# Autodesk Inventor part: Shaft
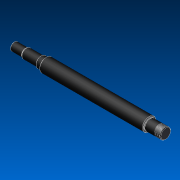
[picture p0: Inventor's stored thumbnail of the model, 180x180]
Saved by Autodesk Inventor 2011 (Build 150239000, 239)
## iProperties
Created: 2011-05
Part Number: Shaft
Material: Steel
Document SubType Name: Modeling
Designer: 904Chiaki
Density: 1 g/cm^3
Author: 904Chiaki
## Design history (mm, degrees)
sketch "Main Sketch"
  geometry: L1 (0, 0)-(545.5, 0) reference; L2 (0, 0)-(0, 15); L3 (0, 15)-(45, 15); L4 (45, 15)-(45, 17.5); L5 (45, 17.5)-(100, 17.5); L6 (100, 17.5)-(100, 20); L7 (100, 20)-(119, 20); L8 (119, 25)-(504.5, 25); L9 (545.5, 20)-(545.5, 0); L10 (504.5, 20)-(545.5, 20); L11 (119, 20)-(119, 25); L12 (504.5, 25)-(504.5, 20)
  constraints: 24 end point, 6 vertical, 2 horizontal
  dimensions: "d3" = 30 diameter of L3 L1 (derived); "d4" = 35 diameter of L5 L1 (derived); "d5" = 40 diameter of L7 L1 (derived); "d6" = 50 diameter of L8 L1 (derived); "d8" = 40 diameter of L10 L1 (derived)
revolve "Revolution1" sketch "Main Sketch" stored, may be unused: angle "d9" = 0 deg
chamfer "Chamfer15" distance "d52" = 1; stored, may be unused: second distance "d53" = 0.125, angle "d54" = 45 deg
chamfer "Chamfer16" distance "d55" = 1; stored, may be unused: second distance "d56" = 0.125, angle "d57" = 45 deg
node "Keyway1"
node "Relief2"
chamfer "Chamfer8" distance "d31" = 1; stored, may be unused: second distance "d32" = 0.125, angle "d33" = 45 deg
node "Relief3"
chamfer "Chamfer2" distance "d13" = 1; stored, may be unused: second distance "d14" = 0.125, angle "d15" = 45 deg
node "Relief1"
workpoint "Work Point1"
hole "Hole1" diameter "d60" = 8; stored, may be unused: countersink angle "d64" = 90 deg, drill point angle "d66" = 118 deg; dims "d58" = 10, "d59" = 10, "d61" = 6, "d62" = 4, "d63" = 2, "d65" = 30
chamfer "Chamfer17" distance "d67" = 1; stored, may be unused: second distance "d68" = 2, angle "d69" = 45 deg
thread "Thread1" dims "d70" = 10, "d71" = 0
sketch "Sketch5"
  geometry: C1 r 20 at (0, 0) reference
extrude "Extrusion1" join sketch "Sketch5" distance "d83" = 20; taper "d84" = 0 deg
chamfer "Chamfer18" distance "d85" = 2; stored, may be unused: second distance "d86" = 2, angle "d87" = 45 deg
thread "Thread2" dims "d88" = 22, "d89" = 0
body "Solid1"
feature "iFeature1:1"
feature "iFeature1:2"
feature "iFeature1:3"
chamfer "Chamfer10" distance "d37" = 1; stored, may be unused: second distance "d38" = 1, angle "d39" = 45 deg
feature "iFeature1:4"
other parameters: "d0" = 0, "d1" = 0, "d2" = 0
